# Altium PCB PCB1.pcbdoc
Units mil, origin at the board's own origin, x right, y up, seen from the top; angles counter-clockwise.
Board outline 2416.05 x 3420.76 mil, 2 copper layers (Top Layer, Bottom Layer); 51 components, 45 nets, 147 pads, 38 vias.
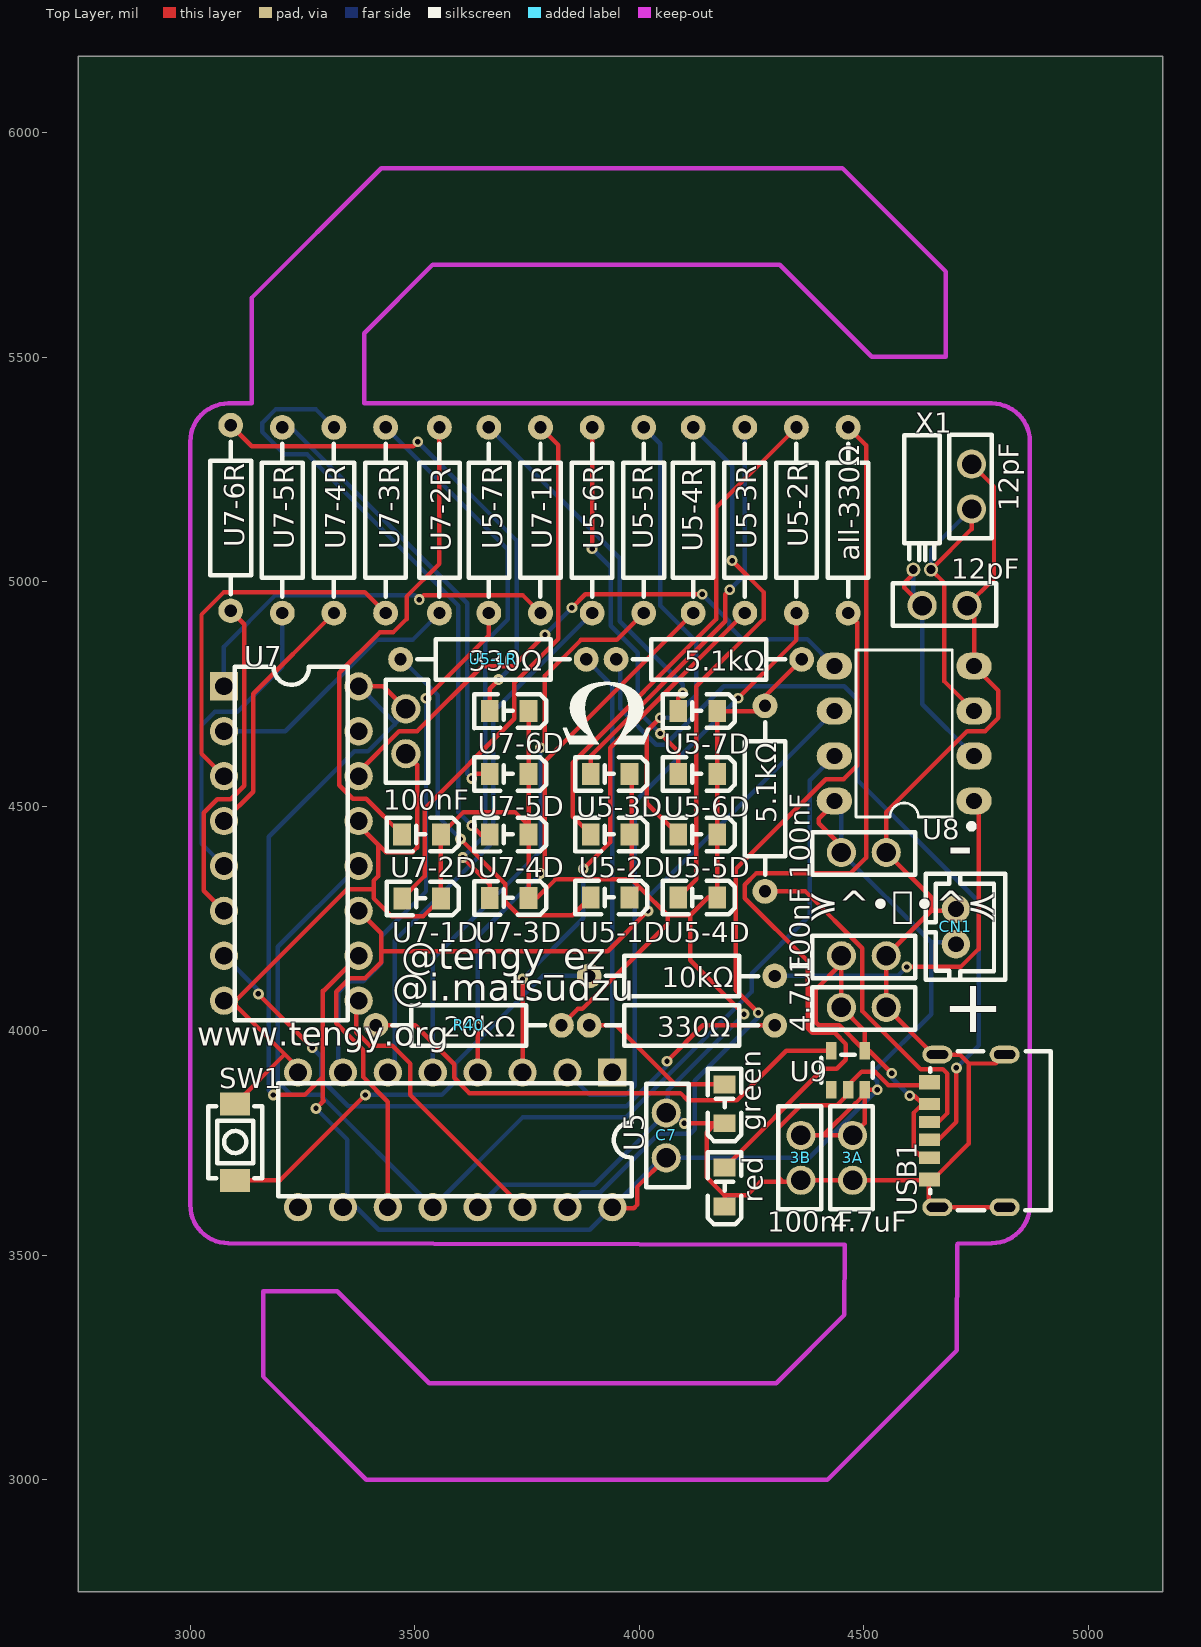
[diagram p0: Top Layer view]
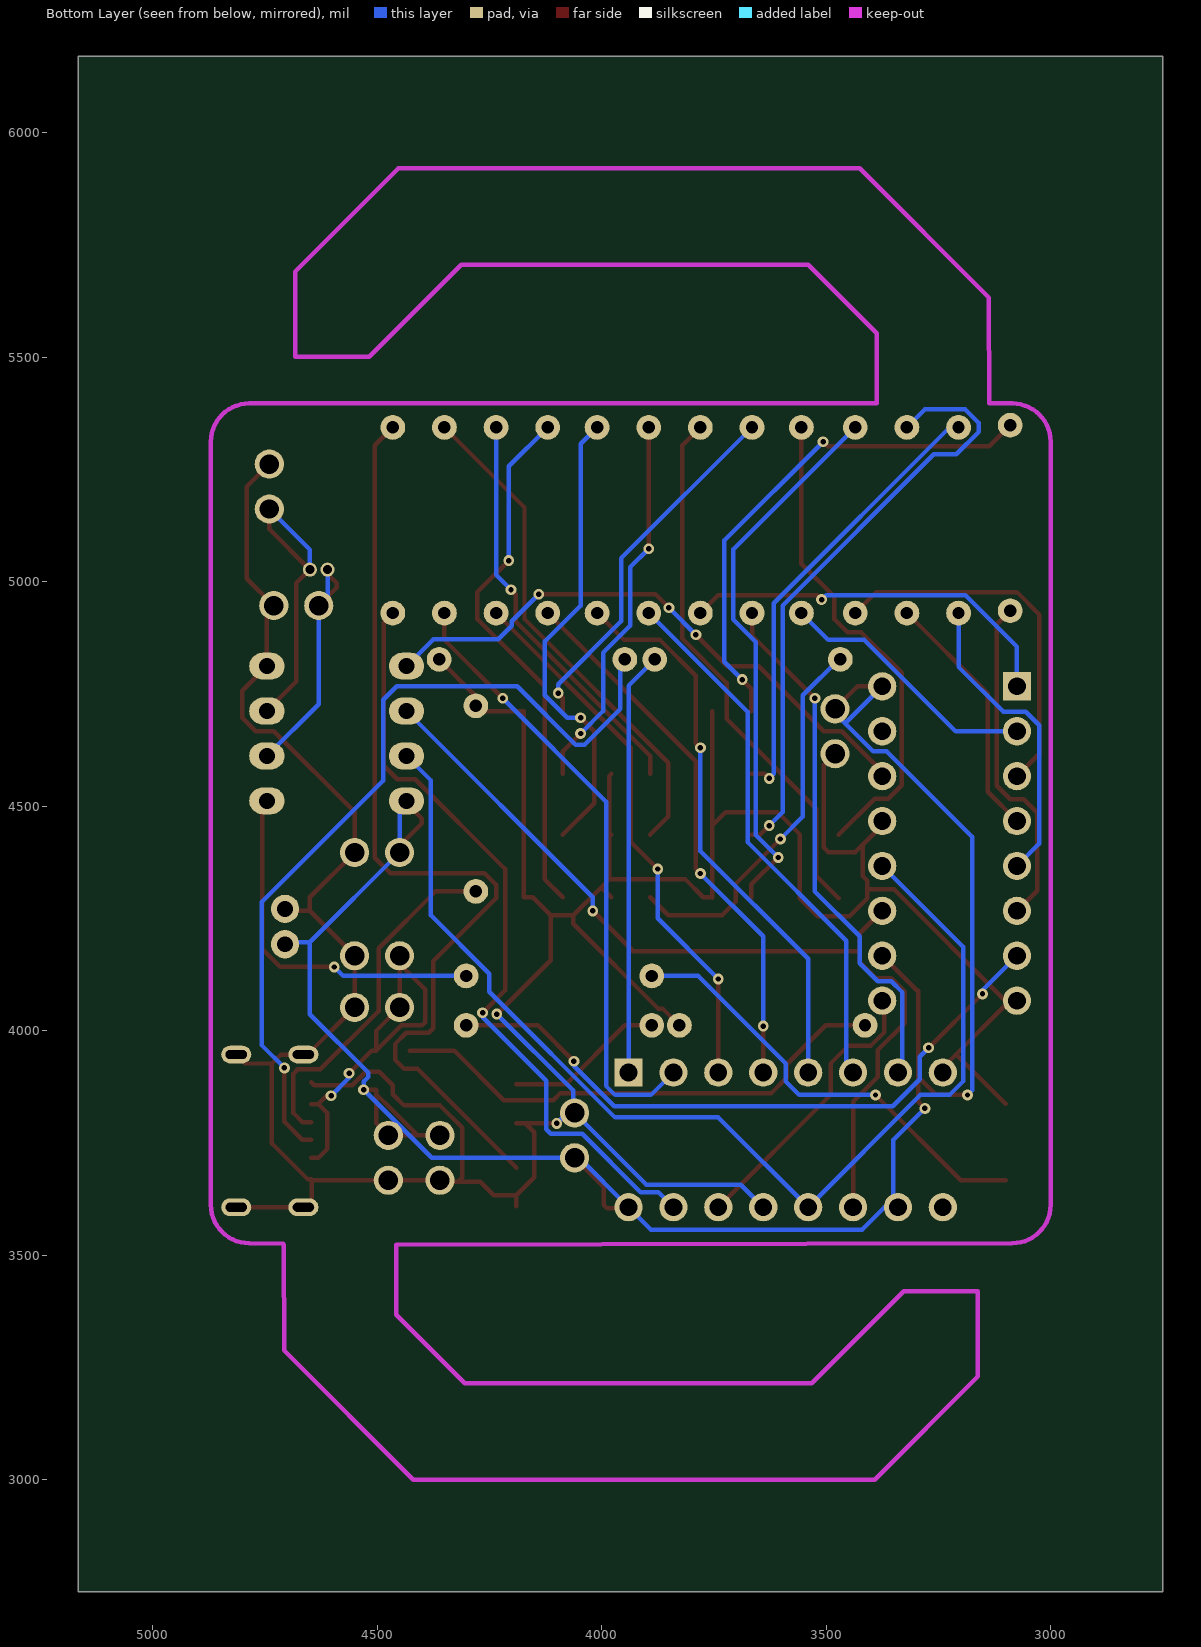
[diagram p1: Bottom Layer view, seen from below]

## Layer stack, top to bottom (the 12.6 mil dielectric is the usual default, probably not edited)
Top Layer: signal copper (thickness not stored)
Dielectric: dielectric 12.6, FR-4, Dk 4.8
Bottom Layer: signal copper (thickness not stored)

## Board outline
5166.05,2750 2750,2750 2750,6170.76 5166.05,6170.76

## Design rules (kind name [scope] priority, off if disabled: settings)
BoardOutlineClearance copperThickness1oz [All] p0: genericclearance=10 ignorepadtopadclearanceinfootprint=FALSE except(0: Arc-SplitContinuation Track-SplitContinuation SMDPad-SplitContinuation THPad-SplitContinuation Via-SplitContinuation Fill-SplitContinuation Poly-SplitContinuation Region-SplitContinuation Text-SplitContinuation; 6: Track-CutoutEdge SMDPad-CutoutEdge THPad-CutoutEdge Via-CutoutEdge Region-CutoutEdge; 11.8: Track-OutlineEdge SMDPad-OutlineEdge THPad-OutlineEdge Via-OutlineEdge Fill-OutlineEdge Region-OutlineEdge Poly-OutlineEdge Text-OutlineEdge Fill-CutoutEdge)
BoardOutlineClearance copperThickness2oz [All] p0: genericclearance=10 ignorepadtopadclearanceinfootprint=FALSE except(0: Arc-SplitContinuation Track-SplitContinuation SMDPad-SplitContinuation THPad-SplitContinuation Via-SplitContinuation Fill-SplitContinuation Poly-SplitContinuation Region-SplitContinuation Text-SplitContinuation; 6: Track-CutoutEdge SMDPad-CutoutEdge THPad-CutoutEdge Via-CutoutEdge Region-CutoutEdge; 11.8: Track-OutlineEdge SMDPad-OutlineEdge THPad-OutlineEdge Via-OutlineEdge Fill-OutlineEdge Region-OutlineEdge Poly-OutlineEdge Text-OutlineEdge Fill-CutoutEdge)
Clearance copperThickness1oz [(InNet('GND') OR InNet('VCC') OR InNet('$1N3175') OR InNet('$1N3221') OR InNet('$1N3267') OR InNet('$1N3313') OR InNet('$1N3359') OR InNet('$1N1454') OR InNet('PIN12') OR InNet('PIN11') OR InNet('$1N1740') OR InNet('$1N7565') OR InNet('$1N7519') OR InNet('$1N7473') OR InNet('$1N7427') OR InNet('$1N7381') OR InNet('$1N7335') OR InNet('$1N7289') OR InNet('$1N8994') OR InNet('$1N8990') OR InNet('$1N10886') OR InNet('$1N10964') OR InNet('$1N10884') OR InNet('$1N10962') OR InNet('$1N11659') OR InNet('$1N11661') OR InNet('$1N11663') OR InNet('$1N11665') OR InNet('$1N11667') OR InNet('$1N11669') OR InNet('$1N11671') OR InNet('$1N11563') OR InNet('$1N11565') OR InNet('$1N11567') OR InNet('$1N11569') OR InNet('$1N11571') OR InNet('$1N11573') OR InNet('$1N11575') OR InNet('$1N11673') OR InNet('$1N13466') OR InNet('$1N13478') OR InNet('$1N15518') OR InNet('$1N15286') OR InNet('$1N16011') OR InNet('$1N16013'))] p1: gap=7 ignorepadtopadclearanceinfootprint=FALSE except(4: Track-Track; 6: Track-SMDPad SMDPad-SMDPad Track-THPad SMDPad-THPad THPad-THPad Track-Via SMDPad-Via THPad-Via Via-Via SMDPad-Fill THPad-Fill Via-Fill Fill-Fill Track-Region SMDPad-Region THPad-Region Via-Region Region-Region Track-Poly SMDPad-Poly THPad-Poly Via-Poly Fill-Poly Region-Poly Poly-Poly Track-Text SMDPad-Text THPad-Text Via-Text Fill-Text Region-Text Poly-Text Text-Text; 6.9: Track-Hole SMDPad-Hole THPad-Hole Via-Hole Fill-Hole Region-Hole Poly-Hole Text-Hole Sheet-Hole; 11.8: Track-Fill Fill-Region Track-Sheet SMDPad-Sheet THPad-Sheet Via-Sheet Fill-Sheet Region-Sheet Poly-Sheet Text-Sheet)
Clearance copperThickness2oz [All] p1: gap=7 ignorepadtopadclearanceinfootprint=FALSE except(6: Track-SMDPad SMDPad-SMDPad Track-THPad SMDPad-THPad THPad-THPad Track-Via SMDPad-Via THPad-Via Via-Via SMDPad-Fill THPad-Fill Via-Fill Fill-Fill Track-Region SMDPad-Region THPad-Region Via-Region Region-Region Track-Poly SMDPad-Poly THPad-Poly Via-Poly Fill-Poly Region-Poly Poly-Poly Track-Text SMDPad-Text THPad-Text Via-Text Fill-Text Region-Text Poly-Text Text-Text; 6.9: Track-Hole SMDPad-Hole THPad-Hole Via-Hole Fill-Hole Region-Hole Poly-Hole Text-Hole Sheet-Hole; 8: Track-Track; 11.8: Track-Fill Fill-Region Track-Sheet SMDPad-Sheet THPad-Sheet Via-Sheet Fill-Sheet Region-Sheet Poly-Sheet Text-Sheet)
DiffPairsRouting differentialPair [All] p1: maxuncoupledlength=10 minlimit=6 maxlimit=6 mostfreqgap=6 toplayer_minwidth=5 toplayer_prefwidth=10 toplayer_maxwidth=100 bottomlayer_minwidth=5 bottomlayer_prefwidth=10 bottomlayer_maxwidth=100
PasteMaskExpansion pasteMaskExpansion [All] p1: expansion=0
PlaneConnect innerPlane [All] p1: planeconnectstyle=Relief reliefexpansion=20 reliefentries=4 reliefconductorwidth=10 reliefairgap=10
PolygonConnect copperRegion [All] p1: connectstyle=Relief reliefentries=4 reliefconductorwidth=10 polygonreliefangle="90 Angle" airgapwidth=10
RoutingVias viaSize [All] p1: viastyle="Through Hole" holewidth=12.0078 minholewidth=11.811 maxholewidth=248.0314 width=24.0158 minwidth=19.685 maxwidth=393.7008
SolderMaskExpansion solderMaskExpansion [All] p1: useseparateexpansions=TRUE expansion=2 expansionbottom=2
Width copperThickness1oz [All] p1: maxlimit=100 minlimit=5 preferedwidth=10
Width copperThickness2oz [All] p1: maxlimit=100 minlimit=8 preferedwidth=10

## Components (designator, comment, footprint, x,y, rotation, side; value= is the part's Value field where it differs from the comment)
3A "4.7uF" CAP-TH_L5.8-W2.4-P2.54-D0.6 4475,3716.92 r270 top
3B "100nF" CAP-TH_L5.8-W2.4-P2.54-D0.6 4360,3716.92 r270 top
4.7uF "CC1H104ZA1ED3F5P1100" CAP-TH_L5.8-W2.4-P2.54-D0.6 4500,4051.92 r0 top
5.1kΩ "MF1/4W-1KΩ±1%T52" RES-TH_BD2.3-L6.5-P10.50-D0.5 4155,4826.92 r0 top
5.1kΩ "MF1/4W-1KΩ±1%T52" RES-TH_BD2.3-L6.5-P10.50-D0.5 4280,4516.92 r90 top
10kΩ "MF1/4W-1KΩ±1%T52" RES-TH_BD2.3-L6.5-P10.50-D0.5 4095,4121.92 r0 top
12pF "CC1H104ZA1ED3F5P1100" CAP-TH_L5.8-W2.4-P2.54-D0.6 4740,5211.92 r270 top
12pF "CC1H104ZA1ED3F5P1100" CAP-TH_L5.8-W2.4-P2.54-D0.6 4680,4946.92 r180 top
100nF "CC1H104ZA1ED3F5P1100" CAP-TH_L5.8-W2.4-P2.54-D0.6 4500,4396.92 r0 top
100nF "CC1H104ZA1ED3F5P1100" CAP-TH_L5.8-W2.4-P2.54-D0.6 3480,4666.92 r90 top
100nF "CC1H104ZA1ED3F5P1100" CAP-TH_L5.8-W2.4-P2.54-D0.6 4500,4166.92 r0 top
330Ω "MF1/4W-1KΩ±1%T52" RES-TH_BD2.3-L6.5-P10.50-D0.5 4095,4011.92 r0 top
all-330Ω "MF1/4W-1KΩ±1%T52" RES-TH_BD2.3-L6.5-P10.50-D0.5 4465,5136.92 r90 top
C7 "CC1H104ZA1ED3F5P1100" CAP-TH_L5.8-W2.4-P2.54-D0.6 4060,3766.92 r90 top
CN1 "B2B-PH-K-S-GW" CONN-TH_B2B-PH-K-S 4705,4231.92 r270 top
green "TJ-S2012EX8T5ALC2R-A5" LED0805-RD 4190,3836.92 r90 top
R40 "20kΩ" RES-TH_BD2.3-L6.5-P10.50-D0.5 3620,4011.92 r0 top
red "TJ-S2012EX8T5ALC2R-A5" LED0805-RD 4190,3651.92 r90 top
SW1 "HX 3x4x2-2P-1.6N TACTILE SWITCH" KEY-SMD_L4.0-W3.0-LS4.9-1 3100,3751.92 r270 top
U5 "74HC595N" DIP-16_L19.8-W6.5-P2.54-LS7.6-BL 3590,3756.92 r180 top
U5-1D "TJ-S2012EX8T5ALC2R-A5" LED0805-RD 3935,4296.92 r180 top
U5-1R "330Ω" RES-TH_BD2.3-L6.5-P10.50-D0.5 3675,4826.92 r0 top
U5-2D "TJ-S2012EX8T5ALC2R-A5" LED0805-RD 3935,4436.92 r180 top
U5-2R "MF1/4W-1KΩ±1%T52" RES-TH_BD2.3-L6.5-P10.50-D0.5 4350,5136.92 r270 top
U5-3D "TJ-S2012EX8T5ALC2R-A5" LED0805-RD 3935,4571.92 r180 top
U5-3R "MF1/4W-1KΩ±1%T52" RES-TH_BD2.3-L6.5-P10.50-D0.5 4235,5136.92 r270 top
U5-4D "TJ-S2012EX8T5ALC2R-A5" LED0805-RD 4130,4296.92 r180 top
U5-4R "MF1/4W-1KΩ±1%T52" RES-TH_BD2.3-L6.5-P10.50-D0.5 4120,5136.92 r270 top
U5-5D "TJ-S2012EX8T5ALC2R-A5" LED0805-RD 4130,4436.92 r180 top
U5-5R "MF1/4W-1KΩ±1%T52" RES-TH_BD2.3-L6.5-P10.50-D0.5 4010,5136.92 r270 top
U5-6D "TJ-S2012EX8T5ALC2R-A5" LED0805-RD 4130,4571.92 r180 top
U5-6R "MF1/4W-1KΩ±1%T52" RES-TH_BD2.3-L6.5-P10.50-D0.5 3895,5136.92 r270 top
U5-7D "TJ-S2012EX8T5ALC2R-A5" LED0805-RD 4130,4711.92 r180 top
U5-7R "MF1/4W-1KΩ±1%T52" RES-TH_BD2.3-L6.5-P10.50-D0.5 3665,5136.92 r270 top
U7 "74HC595N" DIP-16_L19.8-W6.5-P2.54-LS7.6-BL 3225,4416.92 r270 top
U7-1D "TJ-S2012EX8T5ALC2R-A5" LED0805-RD 3515.08,4294.52 r180 top
U7-1R "MF1/4W-1KΩ±1%T52" RES-TH_BD2.3-L6.5-P10.50-D0.5 3780,5136.92 r270 top
U7-2D "TJ-S2012EX8T5ALC2R-A5" LED0805-RD 3515,4436.92 r180 top
U7-2R "MF1/4W-1KΩ±1%T52" RES-TH_BD2.3-L6.5-P10.50-D0.5 3555,5136.92 r270 top
U7-3D "TJ-S2012EX8T5ALC2R-A5" LED0805-RD 3710.08,4295.89 r180 top
U7-3R "MF1/4W-1KΩ±1%T52" RES-TH_BD2.3-L6.5-P10.50-D0.5 3435,5136.92 r270 top
U7-4D "TJ-S2012EX8T5ALC2R-A5" LED0805-RD 3710,4436.92 r180 top
U7-4R "MF1/4W-1KΩ±1%T52" RES-TH_BD2.3-L6.5-P10.50-D0.5 3320,5136.92 r270 top
U7-5D "TJ-S2012EX8T5ALC2R-A5" LED0805-RD 3710,4571.92 r180 top
U7-5R "MF1/4W-1KΩ±1%T52" RES-TH_BD2.3-L6.5-P10.50-D0.5 3205,5136.92 r270 top
U7-6D "TJ-S2012EX8T5ALC2R-A5" LED0805-RD 3710,4711.92 r180 top
U7-6R "MF1/4W-1KΩ±1%T52" RES-TH_BD2.3-L6.5-P10.50-D0.5 3090,5141.92 r270 top
U8 "ATTINY85-20PU" PDIP-8_L9.3-W6.4-P2.54-LS7.9-BL-1 4590,4661.92 r90 top
U9 "MCP73831T-2DCI/OT" SOT-23-5_L2.9-W1.6-P0.95-LS2.8-BL 4465,3911.92 r0 top
USB1 "TYPE-C 6P(073)" TYPE-C-SMD_TYPE-C-6P-073 4730,3776.92 r90 top
X1 "TAXD32768K2BGBBZT2S" OSC-TH_BD2.0-P0.70-D0.3 4630,5026.92 r270 top

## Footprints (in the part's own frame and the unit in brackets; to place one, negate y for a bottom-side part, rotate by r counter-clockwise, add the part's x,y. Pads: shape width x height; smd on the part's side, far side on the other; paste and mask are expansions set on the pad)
CAP-TH_L5.8-W2.4-P2.54-D0.6 [mm]
  round 1.65 hole 1.1: 1(-1.27,0) 2(1.27,0)
  silkscreen extent -2.92,-1.27 2.92,1.14
CONN-TH_B2B-PH-K-S [mm]
  round 1.6 hole 0.9: 1(1,0) 2(-1,0)
  silkscreen extent -3,-1.7 3,2.8
DIP-16_L19.8-W6.5-P2.54-LS7.6-BL [mm]
  rect 1.6x1.6 hole 1: 1(-8.89,-3.81)
  round 1.6 hole 1 copper offset 0,0: 2(-6.35,-3.81) 3(-3.81,-3.81) 4(-1.27,-3.81) 5(1.27,-3.81) 6(3.81,-3.81) 7(6.35,-3.81) 8(8.89,-3.81) 9(8.89,3.81) 10(6.35,3.81) 11(3.81,3.81) 12(1.27,3.81) 13(-1.27,3.81) 14(-3.81,3.81) 15(-6.35,3.81) 16(-8.89,3.81)
  silkscreen extent -10,-3.2 10,3.2
KEY-SMD_L4.0-W3.0-LS4.9-1 [mm]
  rect 1.3x1.7 smd: 1(-2.159,0) 2(2.159,0)
  silkscreen extent -2.03,-1.52 2.03,1.52
LED0805-RD [mm]
  rect 1x1.25 smd: 1(-1.1,0) 2(1.1,0)
  silkscreen extent -2.1,-0.95 1.98,0.96
OSC-TH_BD2.0-P0.70-D0.3 [mm]
  round 0.8 hole 0.5: 1(0,0.5) 2(0,-0.5)
  silkscreen extent -7.6,-1 -0.54,1
PDIP-8_L9.3-W6.4-P2.54-LS7.9-BL-1 [mm]
  oval 1.524x2 hole 0.9: 1(-3.81,-3.95) 2(-1.27,-3.95) 3(1.27,-3.95) 4(3.81,-3.95) 5(3.81,3.95) 6(1.27,3.95) 7(-1.27,3.95) 8(-3.81,3.95)
  silkscreen extent -5.4,-3.95 4.73,2.72
RES-TH_BD2.3-L6.5-P10.50-D0.5 [mm]
  round 1.4 hole 0.7: 1(-5.25,0) 2(5.25,0)
  silkscreen extent -4.32,-1.15 4.32,1.15
SOT-23-5_L2.9-W1.6-P0.95-LS2.8-BL [mm]
  rect 0.6x1 smd: 1(-0.95,-1.1) 2(0,-1.1) 3(0.95,-1.1) 4(0.95,1.1) 5(-0.95,1.1)
  silkscreen extent -1.52,-0.7 1.4,0.89
TYPE-C-SMD_TYPE-C-6P-073 [mm]
  oval 1x1.7 hole 0.5 slot 1.2 at 90 deg: 7(-4.32,-2.125) 7(-4.32,1.675) 7(4.32,-2.125) 7(4.32,1.675)
  rect 0.7x1.2 smd: A5(-0.5,2.125) A9(1.52,2.125) B5(0.5,2.125) B9(-1.52,2.125)
  rect 0.8x1.2 smd: A12(2.75,2.125) B12(-2.75,2.125)
  silkscreen extent -4.5,-4.73 4.5,2.08

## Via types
v1: diameter 24.02, hole 12.01, Top Layer to Bottom Layer, 38 vias

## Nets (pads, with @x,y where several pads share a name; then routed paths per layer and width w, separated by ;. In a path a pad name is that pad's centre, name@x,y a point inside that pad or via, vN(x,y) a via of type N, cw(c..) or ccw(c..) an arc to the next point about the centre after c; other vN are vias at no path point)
$1N1454: U7.14 U8.5 | length 1305.2
  Top Layer w10: U7.14 3375,4576.92 3465,4666.92 3505,4666.92 3650,4811.92 3720,4811.92 v1(3790,4881.92) ; v1(3850,4941.92) 3880,4971.92 v1(4140,4971.92)
  Bottom Layer w10: v1(3790,4881.92) v1(3850,4941.92) ; v1(4140,4971.92) 4200,4911.92 4200,4901.92 4230,4871.92 4374.49,4871.92 U8.5
$1N1740: U5.14 U7.9 | length 644.6
  Top Layer w10: U7.9 3370,4061.92 3370,3996.92 3400,3966.92 3450,3966.92 3490,3926.92 3490,3856.92 U5.14
$1N3175: U5-5D.2 U5-5R.1 | length 1047.2
  Top Layer w10: v1(4046.69,4696.92) 4016.69,4666.92 4016.69,4506.92 U5-5D.2
  Bottom Layer w10: U5-5R.1 4046.69,5306.92 4046.69,4946.92 4126.69,4866.92 4126.69,4746.92 4076.69,4696.92 v1(4046.69,4696.92)
$1N3221: U5-4D.2 U5-4R.1 | length 1190.3
  Top Layer w10: U5-4D.2 4126.69,4336.92 4126.69,4766.92 4276.69,4916.92 4276.69,4976.92 v1(4206.69,5046.92)
  Bottom Layer w10: U5-4R.1 4206.69,5256.92 v1(4206.69,5046.92)
$1N3267: U5-3D.2 U5-3R.1 | length 913.9
  Top Layer w10: U5-3D.2 3891.69,4611.92 4191.69,4911.92 4191.69,4971.92 v1(4201.69,4981.92)
  Bottom Layer w10: v1(4201.69,4981.92) 4235,5015.22 U5-3R.1
$1N3313: U5-2D.2 U5-2R.1 | length 1129.7
  Top Layer w10: U5-2D.2 3851.69,4476.92 3851.69,4596.92 4171.69,4916.92 4171.69,5165.3 U5-2R.1
$1N3359: U5-1D.2 U5-1R.1 | length 857.6
  Top Layer w10: v1(3601.69,4426.92) 3701.69,4326.92 3701.69,4286.92 3731.69,4256.92 3851.69,4256.92 U5-1D.2
  Bottom Layer w10: U5-1R.1 3471.69,4826.92 3551.69,4746.92 3551.69,4476.92 v1(3601.69,4426.92)
$1N7289: U7-1D.2 U7-1R.1 | length 1209.9
  Top Layer w10: U7-1D.2 3521.77,4344.52 3521.77,4494.52 3721.77,4694.52 3721.77,4774.52 3820,4872.75 3820,5303.61 U7-1R.1
$1N7335: U7-2D.2 U7-2R.1 | length 1092.3
  Top Layer w10: U7-2D.2 3391.69,4516.92 3361.69,4516.92 3331.69,4546.92 3331.69,4796.92 3421.69,4886.92 3451.69,4886.92 3481.69,4916.92 3481.69,4966.92 3555,5040.22 U7-2R.1
$1N7381: U7-3D.2 U7-3R.1 | length 1226.6
  Top Layer w10: v1(3606.77,4385.89) 3666.77,4325.89 U7-3D.2
  Bottom Layer w10: U7-3R.1 3706.77,5071.84 3706.77,4915.89 3656.77,4865.89 3656.77,4435.89 v1(3606.77,4385.89)
$1N7427: U7-4D.2 U7-4R.1 | length 1356.6
  Top Layer w10: v1(3626.69,4456.92) 3646.69,4436.92 U7-4D.2
  Bottom Layer w10: U7-4R.1 3280,5383.61 3190,5383.61 3160,5353.61 3160,5333.61 3210,5283.61 3260,5283.61 3596.69,4946.92 3596.69,4486.92 v1(3626.69,4456.92)
$1N7473: U7-5D.2 U7-5R.1 | length 1012.2
  Top Layer w10: v1(3626.69,4561.92) 3636.69,4571.92 U7-5D.2
  Bottom Layer w10: U7-5R.1 3225,5343.61 3616.69,4951.92 3616.69,4571.92 v1(3626.69,4561.92)
$1N7519: U7-6D.2 U7-6R.1 | length 1156.2
  Top Layer w10: U7-6R.1 3136.69,5301.92 3496.69,5301.92 v1(3506.69,5311.92) ; U7-6D.2 3666.69,4761.92 v1(3686.69,4781.92)
  Bottom Layer w10: v1(3506.69,5311.92) 3726.69,5091.92 3726.69,4821.92 v1(3686.69,4781.92)
$1N7565: 330Ω.1 green.2 | length 356.2
  Top Layer w10: 330Ω.1 3948.3,4011.92 4080,3880.23 green.2
$1N8990: U5-6D.2 U5-6R.1 | length 851.1
  Top Layer w10: v1(3895,5073.61) U5-6R.1 ; v1(4046.69,4661.92) 4086.69,4621.92 U5-6D.2
  Bottom Layer w10: v1(3895,5073.61) 3936.69,5031.92 3936.69,4901.92 3996.69,4841.92 3996.69,4711.92 v1(4046.69,4661.92)
$1N8994: U5-7D.2 U5-7R.1 | length 814.6
  Top Layer w10: U5-7D.2 4086.69,4741.92 v1(4096.69,4751.92)
  Bottom Layer w10: U5-7R.1 3956.69,5051.92 3956.69,4911.92 4096.69,4771.92 v1(4096.69,4751.92)
$1N10884: all-330Ω.1 U5.15 | length 1728.1
  Top Layer w10: v1(4265,4040.23) 4215,4090.23 4215,4360.23 4415,4560.23 4455,4560.23 4485,4590.23 4485,4910.23 all-330Ω.1
  Bottom Layer w10: U5.15 3873.31,3640.23 3913.31,3640.23 4043.31,3770.23 4113.31,3770.23 4123.31,3780.23 4123.31,3888.54 4265,4030.23 v1(4265,4040.23)
$1N10886: all-330Ω.2 red.2 | length 2151.7
  Top Layer w10: red.2 4410,3915.23 4440,3915.23 4460,3935.23 4460,3970.23 4435,3995.23 4385,3995.23 4375,4005.23 4375,4155.23 4235,4295.23 4235,4325.23 4260.98,4351.21 4470.98,4351.21 4505,4385.23 4505,5303.61 all-330Ω.2
$1N10962: 10kΩ.2 U8.1 | length 812.8
  Top Layer w10: v1(4595.51,4141.92) 4715.51,4141.92 4755.51,4181.92 4755.51,4501.92 U8.1
  Bottom Layer w10: 10kΩ.2 4575.51,4121.92 v1(4595.51,4141.92)
$1N10964: 10kΩ.1 SW1.2 | length 1000.2
  Top Layer w10: SW1.2 3200,3666.92 v1(3390,3856.92)
  Bottom Layer w10: v1(3390,3856.92) 3560,3856.92 3590,3886.92 3590,3926.92 3785,4121.92 10kΩ.1
$1N11563: U5-1R.2 U5.1 | length 944.2
  Bottom Layer w10: U5-1R.2 3940,4768.61 U5.1
$1N11565: U5-2R.2 U5.2 | length 1381.4
  Top Layer w10: v1(4220,4740.23) 4350,4870.23 U5-2R.2
  Bottom Layer w10: U5.2 3890,3856.92 3970,3856.92 3990,3876.92 3990,4510.23 v1(4220,4740.23)
$1N11567: U5-3R.2 U5.3 | length 1228.3
  Top Layer w10: U5.3 v1(3740,4115.23) ; v1(3875,4360.23) 3935,4420.23 3935,4630.23 U5-3R.2
  Bottom Layer w10: v1(3740,4115.23) 3875,4250.23 v1(3875,4360.23)
$1N11569: U5-4R.2 U5.4 | length 1222.1
  Top Layer w10: U5.4 v1(3640,4010.23) ; v1(3780,4350.23) 3790,4360.23 3790,4600.23 U5-4R.2
  Bottom Layer w10: v1(3640,4010.23) 3640,4210.23 v1(3780,4350.23)
$1N11571: U5-5R.2 U5.5 | length 1264.9
  Top Layer w10: v1(3780,4630.23) 3790,4640.23 3790,4790.23 3870,4870.23 3950,4870.23 U5-5R.2
  Bottom Layer w10: U5.5 3540,4160.23 3780,4400.23 v1(3780,4630.23)
$1N11573: U5-6R.2 U5.6 | length 1211.8
  Bottom Layer w10: U5.6 3455,3921.92 3455,4200.23 3675,4420.23 3675,4710.23 U5-6R.2
$1N11575: U5-7R.2 U5.7 | length 1183.8
  Top Layer w10: v1(3525,4740.23) 3665,4880.23 U5-7R.2
  Bottom Layer w10: U5.7 3330,3916.92 3330,4085.23 3355,4110.23 3385,4110.23 3425,4150.23 3425,4210.23 3525,4310.23 v1(3525,4740.23)
$1N11659: U7-1R.2 U7.1 | length 865.8
  Top Layer w10: v1(3510,4960.23) 3520,4970.23 3740,4970.23 U7-1R.2
  Bottom Layer w10: U7.1 3075,4855.23 3190,4970.23 3500,4970.23 v1(3510,4960.23)
$1N11661: U7-2R.2 U7.2 | length 589.1
  Bottom Layer w10: U7.2 3211.69,4666.92 3415,4870.23 3495,4870.23 U7-2R.2
$1N11663: U7-3R.2 U7.3 | length 830.8
  Top Layer w10: U7.3 3025,4616.92 3025,4926.92 3075,4976.92 3388.31,4976.92 U7-3R.2
$1N11665: U7-4R.2 U7.4 | length 564.8
  Top Layer w10: U7.4 3140,4531.92 3140,4750.23 U7-4R.2
$1N11667: U7-5R.2 U7.5 | length 687.9
  Bottom Layer w10: U7.5 3025,4416.92 3025,4680.23 3055,4710.23 3105,4710.23 3205,4810.23 U7-5R.2
$1N11669: U7-6R.2 U7.6 | length 754.2
  Top Layer w10: U7.6 3030,4311.92 3030,4485.23 3060,4515.23 3090,4515.23 3120,4545.23 3120,4905.23 U7-6R.2
$1N11671: 330Ω.2 U7.7 | length 1480
  Top Layer w10: v1(3151.69,4081.92) v1(3271.69,3961.92) ; v1(4061.69,3931.92) 4141.69,4011.92 330Ω.2
  Bottom Layer w10: U7.7 3151.69,4090.23 v1(3151.69,4081.92) ; v1(3271.69,3961.92) 3291.69,3941.92 3291.69,3891.92 3351.69,3831.92 3971.69,3831.92 4061.69,3921.92 v1(4061.69,3931.92)
$1N11673: U7.15
$1N13466: 12pF.2@4630,4946.92 U8.2 X1.2 | length 576
  Top Layer w10: X1.2 4610.31,5017.24 4590,4996.92 4590,4986.92 12pF.2@4630,4946.92
  Bottom Layer w10: X1.2 4610.31,4966.61 4630,4946.92 4630,4727.43 U8.2
$1N13478: 12pF.2@4740,5161.92 U8.3 X1.1 | length 699.5
  Top Layer w10: 12pF.2@4740,5161.92 4740,5117.24 X1.1 4679.69,4996.92 4679.69,4777.75 U8.3
  Bottom Layer w10: X1.1 4649.69,5071.61 12pF.2@4740,5161.92
$1N15286: 4.7uF.1 100nF.1@4450,4166.92 U9.4 USB1.A9 USB1.B9 | length 873.7
  Top Layer w10: 100nF.1@4450,4166.92 100nF.1@4450,4148.99 ; v1(4562.4,3905.23) 4512.4,3955.23 U9.4 ; v1(4602.4,3855.23) 4612.4,3855.23 USB1.A9@4630.87,3836.76 ; USB1.B9 4630.55,3717.08 4610.87,3736.76 4610.87,3816.76 USB1.A9@4630.87,3836.76 ; USB1.A9 USB1.A9@4630.87,3836.76 ; 100nF.1@4450,4148.99 4392.93,4091.92 4392.93,4018.99 4400,4011.92 4445.71,4011.92 U9.4 ; 100nF.1@4450,4148.99 4.7uF.1 4502.4,3999.52 U9.4
  Bottom Layer w10: v1(4562.4,3905.23) 4562.4,3895.23 v1(4602.4,3855.23)
$1N15518: R40.1 U9.5 | length 1146.5
  Top Layer w10: R40.1 3500.91,4011.92 3587.6,3925.23 3587.6,3895.23 3621.62,3861.22 4091.62,3861.22 4107.6,3845.23 4217.6,3845.23 4327.6,3955.23 U9.5
$1N16011: 5.1kΩ.1@4280,4310.23 USB1.B5 | length 792.2
  Top Layer w10: 5.1kΩ.1@4280,4310.23 4370,4310.23 4496.34,4183.9 4496.34,4043.9 4626.34,3913.9 4676.34,3913.9 4686.34,3903.9 4686.34,3816.61 4666.34,3796.61 USB1.B5
$1N16013: 5.1kΩ.1@3948.31,4826.92 USB1.A5 | length 1890.6
  Top Layer w10: USB1.A5 4666.34,3757.24 4706.34,3797.24 v1(4706.34,3917.24)
  Bottom Layer w10: 5.1kΩ.1@3948.31,4826.92 3957.99,4817.24 3957.99,4717.24 4037.99,4637.24 4057.99,4637.24 4187.99,4767.24 4456.34,4767.24 4486.34,4737.24 4486.34,4557.24 4756.34,4287.24 4756.34,3967.24 v1(4706.34,3917.24)
GND: 3A.2 3B.2 4.7uF.2 5.1kΩ.2 12pF.1 100nF.1@3480,4616.92 100nF.2@4550,4166.92 100nF.2@4550,4396.92 C7.2 CN1.2 green.1 R40.2 red.1 SW1.1 U5-1D.1 U5-2D.1 U5-3D.1 U5-4D.1 U5-5D.1 U5-6D.1 U5-7D.1 U5.8 U5.13 U7-1D.1 U7-2D.1 U7-3D.1 U7-4D.1 U7-5D.1 U7-6D.1 U7.8 U7.13 U8.4 U9.2 USB1.7 USB1.A12 USB1.B12 | length 8883.4
  Top Layer w10: U7.8 U7.8@3100.79,4066.92 ; SW1.1 3210,3946.92 3210.79,3946.92 ; U5.8 3240,3917.72 3210.79,3946.92 ; U7.13 3375,4457.91 3418.39,4414.52 ; 100nF.1@3480,4616.92 3505,4591.92 3505,4407.91 3495,4397.91 3435,4397.91 3418.39,4414.52 ; U7-1D.1@3558.31,4294.6 U7-2D.1 3608.31,4486.92 3723.31,4486.92 U7-4D.1@3753.31,4456.92 ; U7-1D.1 3518.39,4254.52 3448.39,4254.52 3408.39,4294.52 3408.39,4314.52 ; U7-4D.1 U7-4D.1@3753.31,4456.92 ; U7-6D.1 U7-5D.1 U7-4D.1@3753.31,4456.92 ; U7-4D.1@3753.39,4436.84 U7-3D.1 3754.42,4296.92 3773.31,4296.92 3813.31,4336.92 3983.31,4336.92 ; R40.2 3863.31,4048.54 3873.31,4048.54 4063.31,4238.54 4063.31,4256.92 ; U5-1D.1 3998.31,4316.92 4003.31,4316.92 ; U5-2D.1 U5-2D.1@3983.31,4436.92 ; U5-3D.1 3983.31,4566.92 U5-2D.1@3983.31,4436.92 ; v1(4099.94,3793.61) green.1@4169.94,3793.61 ; red.1@4189.94,3608.67 4189.94,3633.61 ; green.1 green.1@4169.94,3793.61 ; v1(4233.31,4036.92) 4113.31,4156.92 4113.31,4256.92 ; 5.1kΩ.2@4361.69,4826.92 4280,4745.23 4280,4723.61 4268.31,4711.92 U5-7D.1 U5-6D.1 U5-5D.1 U5-4D.1 4153.31,4296.92 4113.31,4256.92 ; USB1.A12 4639.76,3878.61 4555,3878.61 4525,3908.61 4495,3908.61 4465,3878.61 U9.2 4465,3858.67 4439.94,3833.61 4359.94,3833.61 4309.94,3783.61 4309.94,3673.61 4319.94,3663.61 ; CN1.2 4700.63,4266.92 4650,4266.92 ; 12pF.1@4740,5261.92 4790,5211.92 4790,5006.92 4730,4946.92 4745.51,4931.41 U8.4 4800,4757.43 4800,4696.92 4770,4666.92 4730,4666.92 4550,4486.92 4550,4396.92 4650,4296.92 4650,4266.92 ; USB1.7@4813.66,3606.85 4664.06,3606.85 4645,3625.9 USB1.B12@4645,3666.92 ; USB1.7@4813.66,3947 4793.66,3927 4734.06,3927 ; U7.8@3100.79,4066.92 3348.39,4314.52 3408.39,4314.52 ; U7.8@3100.79,4066.92 3100.79,4056.92 3210.79,3946.92 ; 3408.39,4314.52 3408.39,4334.52 3418.39,4344.52 3418.39,4414.52 ; 3983.31,4336.92 U5-2D.1@3983.31,4436.92 ; 3983.31,4336.92 4003.31,4316.92 ; 4003.31,4316.92 4063.31,4256.92 ; 4063.31,4256.92 4113.31,4256.92 ; green.1@4169.94,3793.61 4149.94,3773.61 4149.94,3673.61 4189.94,3633.61 ; 4189.94,3633.61 4239.94,3633.61 4269.94,3663.61 4319.94,3663.61 ; 4319.94,3663.61 4356.69,3663.61 3B.2 3A.2 USB1.B12@4645,3666.92 ; USB1.B12@4645,3666.92 USB1.B12 4654.06,3668.66 4734.06,3748.66 4734.06,3927 ; 4650,4266.92 4550,4166.92 4.7uF.2 4654.93,3947 4664.06,3947 4714.06,3947 4734.06,3927
  Bottom Layer w10: U5.13 3690,3656.92 3900,3656.92 C7.2 C7.2@4063.31,3820.23 ; v1(4099.94,3793.61) 4073.31,3820.23 C7.2@4063.31,3820.23 ; v1(4233.31,4036.92) 4063.31,3866.92 C7.2@4063.31,3820.23
PIN11: U5.11 U7.11 U8.6 | length 2038.5
  Top Layer w10: U7.11 3425,4216.92 3425,4176.92 ; U5.11 3440,3841.92 3385,3896.92 3385,3956.92 3325,4016.92 3325,4086.92 3355,4116.92 3389.23,4116.92 3425,4152.69 3425,4176.92 ; v1(4019.49,4266.92) 3929.49,4176.92 3425,4176.92
  Bottom Layer w10: v1(4019.49,4266.92) 4019.49,4296.92 U8.6
PIN12: U5.12 U7.12 U8.7 | length 2525.8
  Bottom Layer w10: U7.12 3195,4186.92 3195,3886.92 3225,3856.92 3290,3856.92 U5.12 3740,3806.92 3970,3806.92 4250,4086.92 4250,4126.92 4380,4256.92 4380,4557.43 U8.7
VCC: 3A.1 3B.1 100nF.1@4450,4396.92 100nF.2@3480,4716.92 C7.1 CN1.1 U5.10 U5.16 U7.10 U7.16 U8.8 U9.3 | length 4923.7
  Top Layer w10: v1(3185,3856.92) 3255,3856.92 3295,3896.92 ; v1(3280,3826.92) 3297.01,3843.93 ; 3295,3843.93 3295,3896.92 ; 3295,4088.93 3295,4086.92 ; U7.10 3295,4086.92 ; U7.16 3430,4766.92 100nF.2@3480,4716.92 ; U5.16 3942.07,3604.85 3987.93,3604.85 3995,3611.92 3995,3651.92 C7.1 ; 3B.1 4410,3766.92 ; U8.8 4434.49,4506.41 4400,4471.92 4400,4461.92 4450,4411.92 100nF.1@4450,4396.92 ; v1(4530,3868.61) U9.3 U9.3@4502.4,3858.98 ; 3295,3896.92 3295,4086.92 ; 4410,3766.92 4481.02,3837.94 4481.36,3837.94 U9.3@4502.4,3858.98 ; 4410,3766.92 3A.1 4502.4,3794.32 U9.3@4502.4,3858.98
  Bottom Layer w10: v1(3185,3856.92) 3175,3866.92 3175,4431.92 3365,4621.92 3395,4621.92 3455,4681.92 ; v1(3280,3826.92) 3350,3756.92 U5.10@3350,3606.92 ; U5.10 U5.10@3350,3606.92 ; U7.16 3455,4686.92 3455,4681.92 ; 100nF.2@3480,4716.92 3480,4706.92 3455,4681.92 ; U8.8 4450,4496.41 4450,4396.92 4650,4196.92 ; CN1.1 4700.63,4196.92 4650,4196.92 ; U5.10@3350,3606.92 3370,3606.92 3420,3556.92 3890,3556.92 U5.16 4050,3716.92 C7.1 4378.31,3716.92 v1(4530,3868.61) 4530,3886.92 4520,3896.92 4520,3906.92 4650,4036.92 4650,4196.92
pads on no net: U5.9 U9.1

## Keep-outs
Board Outline Layer:
  lines w10: 3000,3611.84 ccw(c3085,3611.84) 3085,3526.84 4457.12,3523.84 4456.99,3367.11 4304.87,3215 3531.99,3215 3326.99,3420 3161.99,3420 3161.99,3230 3391.99,3000 4419.12,3000 4707.03,3287.92 4708.01,3523.84 4709.04,3525.42 4785.08,3526.84 ccw(c4785.08,3611.84) 4870.08,3611.84 4870.08,5311.92 ccw(c4785.08,5311.92) 4785.08,5396.92 3387.35,5396.92 3387.48,5553.65 3539.6,5705.76 4312.48,5705.76 4517.48,5500.76 4682.48,5500.76 4682.48,5690.76 4452.48,5920.76 3425.35,5920.76 3137.44,5632.85 3136.46,5396.92 3084.67,5396.92 3085,5396.92 ccw(c3085,5311.92) 3000,5311.92 3000,3611.84

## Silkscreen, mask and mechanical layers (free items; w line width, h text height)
Top Silkscreen Layer:
  region: 3379 vertices and 0 holes, not listed, extent 3830,4637.68 4025,4776.92
  text "-" at 4745,4446.92 h120 r180
  text "≽^•⩊•^≼" at 4375,4251.92 h60
  text "@tengy_ez" at 3470,4136.92 h60
  text "@i.matsudzu" at 3450,4066.92 h60
  text "+" at 4675,3996.92 h120
  text "www.tengy.org" at 3015,3966.92 h54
